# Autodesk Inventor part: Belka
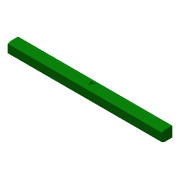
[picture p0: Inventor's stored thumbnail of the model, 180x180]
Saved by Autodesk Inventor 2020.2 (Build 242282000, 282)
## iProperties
Created: 2005-12
Part Number: Belka
Document SubType Name: Modeling
Designer: F.Stasiak
Density: 1 g/cm^3
Material: Ogólny
Appearance: Ciemnozielona
Manager: www.cadconsulting.pl
Company: Fabian Stasiak CAD Consulting
Author: F.Stasiak
Subject: Zbiór ćwiczeń. Autodesk Inventor 2020. Kurs podstawowy
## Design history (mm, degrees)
sketch "Szkic1"
  geometry: L1 (150, 0)-(150, 20); L2 (150, 20)-(-150, 20); L3 (-150, 20)-(-150, 0); L4 (-150, 0)-(150, 0); L5 (0, 0)-(0, 20); L6 (0, 6.892)-(3.932, 15.61); L7 (3.932, 15.61)-(0, 15.61); L8 (0, 15.61)-(-3.932, 15.61); L9 (-3.932, 15.61)-(0, 6.892); 1 further point
  constraints: 18 end point, 4 perpendicular, 2 midpoint, 2 point on line, 1 coincident, 1 collinear, 1 horizontal, 2 other
  dimensions: "d0" = 20 distance of L1.start L1.end; "d4" = 300 distance of L3.end L1.start
extrude "Wyciągnięcie proste1" new body sketch "Szkic1" distance "d1" = 20; taper "d2" = 0 deg
chamfer "Faza1" distance "d5" = 2; stored, may be unused: second distance "d6" = 5, angle "d7" = 45 deg
chamfer "Faza2" distance "d8" = 2; stored, may be unused: second distance "d9" = 5, angle "d10" = 45 deg
node "Bryła1"
node "Korpusy bryłowe"
node "Korpusy powierzchniowe"
